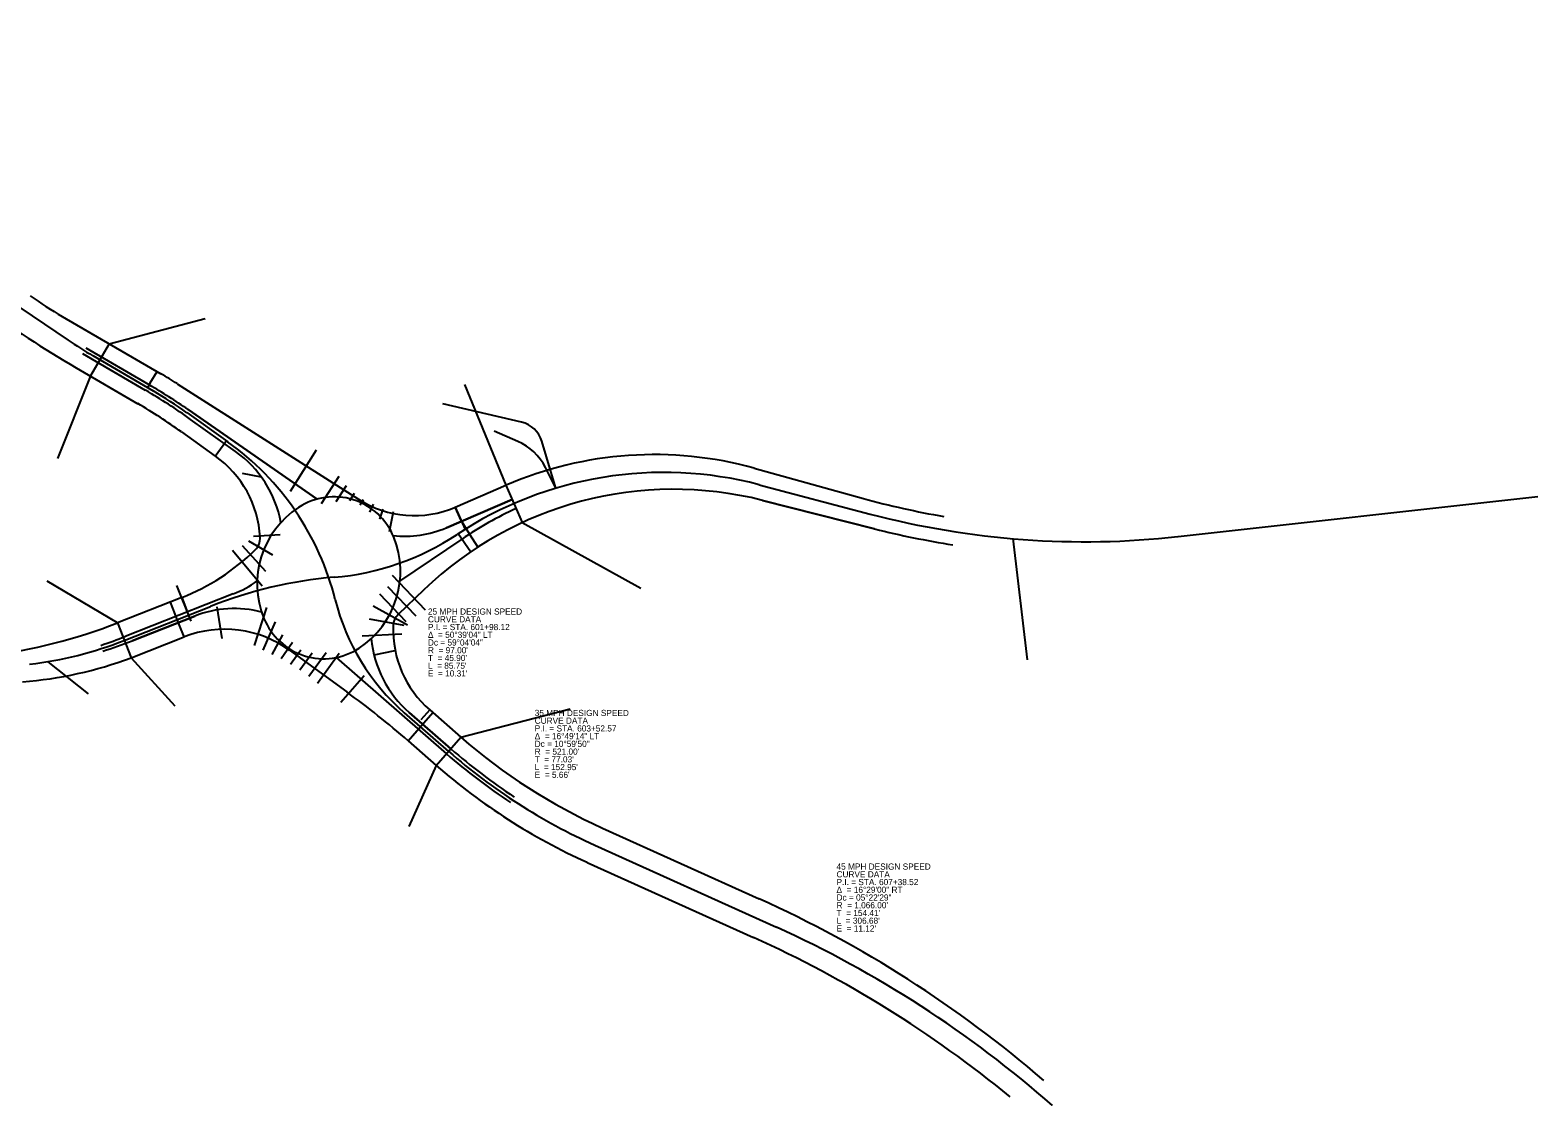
# Model space of a CAD drawing. Extents: x 1600028 to 1602104, y 285464 to 287187.
# Drawn here: x 1600738 to 1602104, y 286222 to 287187 of the extents above; entities that cross this region are included whole.
import ezdxf

# ---------------------------------------------------------------- set-up
doc = ezdxf.new("R2010")
doc.units = 0
for name, color, linetype in [('GE_P_Alignment', 7, 'Continuous'), ('GE_P_Driveway_CL', 7, 'Continuous'), ('SC_Scratch1', 7, 'Continuous'), ('SC_Scratch2', 7, 'Continuous'), ('SC_Scratch3', 7, 'Continuous'), ('SC_Scratch4', 7, 'Continuous'), ('SC_Scratch5', 7, 'Continuous'), ('SC_Scratch6', 7, 'Continuous'), ('SC_Scratch7', 7, 'Continuous')]:
    doc.layers.add(name, color=color, linetype=linetype)

msp = doc.modelspace()

# ---------------------------------------------------------------- linework, layer by layer
at = {"layer": 'GE_P_Alignment'}
for p, q in [((1600356.9, 287187.3), (1600772.5, 286906.6)), ((1600794.8, 286892.6), (1600849.5, 286860.7)), ((1600879.9, 286841), (1600916.9, 286814.6)), ((1601398.3, 286775.7), (1601499, 286749.2)), ((1601777.7, 286728.8), (1602103.6, 286765.1)), ((1600823.2, 286634.8), (1600901.3, 286665.6)), ((1601076.9, 286569.3), (1601117, 286534.3)), ((1601249.5, 286449.3), (1601413.9, 286375.1))]:
    msp.add_line(p, q, dxfattribs=at)
for centre, radius, start, end in [((1600996.4, 287238), 400, 235.9623, 239.7293), ((1600647.8, 286515.2), 400, 54.5316, 59.7293), ((1600771.8, 286611), 250, 14.0171, 54.5316), ((1601311.9, 286446.9), 340, 75.2715, 123.4087), ((1601693.2, 287488.1), 764, 255.2715, 276.3456), ((1600992.5, 286931), 240, 274.977, 303.4087), ((1601048.1, 286293.5), 400, 94.977, 111.5214), ((1601208.4, 286720), 200, 194.0171, 228.8864), ((1600697, 286954.8), 344, 276.7614, 291.5214), ((1601470.8, 286939.7), 538, 228.8864, 245.7068), ((1601002.5, 285463.6), 1000, 48.5834, 65.7068)]:
    msp.add_arc(centre, radius, start, end, dxfattribs=at)
at = {"layer": 'GE_P_Driveway_CL'}
for p, q in [((1601179.8, 286814.9), (1601158.3, 286824.1)), ((1601214.2, 286772.5), (1601204.7, 286791.4)), ((1601628, 286726.9), (1601641, 286617.1))]:
    msp.add_line(p, q, dxfattribs=at)
msp.add_arc((1601160, 286769), 50, 26.7021, 66.684, dxfattribs=at)
at = {"layer": 'SC_Scratch1'}
for p, q in [((1600809.6, 286903.4), (1600792.6, 286874.2)), ((1600846.8, 286867.9), (1600844.4, 286863.6)), ((1600846.8, 286867.9), (1600852.9, 286878.2)), ((1601183.1, 286832.4), (1601111.8, 286849.1)), ((1601183.1, 286832.4), (1601111.8, 286849.1)), ((1601214.2, 286772.5), (1601201.4, 286815.2)), ((1601214.2, 286772.5), (1601201.4, 286815.2)), ((1600905.7, 286801.7), (1600912.7, 286811.5)), ((1601168.9, 286775.3), (1601183.7, 286741.4)), ((1601123.1, 286755.5), (1601131.9, 286735.3)), ((1601128.7, 286742.7), (1601123.1, 286755.5)), ((1601125.8, 286731.5), (1601137.1, 286715)), ((1601128.7, 286742.7), (1601135.9, 286731)), ((1601135.9, 286731), (1601143.5, 286719.2)), ((1600875.3, 286673.6), (1600879.7, 286662.4)), ((1600817, 286650.6), (1600829.5, 286619)), ((1600877.5, 286637.9), (1600873.1, 286649.1)), ((1601080.3, 286543.8), (1601102.7, 286569.4)), ((1601099.9, 286571.8), (1601092, 286562.8)), ((1601080.3, 286543.8), (1601088.2, 286552.8)), ((1601105.9, 286521.5), (1601128.2, 286547.1))]:
    msp.add_line(p, q, dxfattribs=at)
for points in [[(1600905.7, 286801.7), (1600912.7, 286811.5), (1600915.6, 286815.6)], [(1600877.5, 286637.9), (1600873.1, 286649.1), (1600871.3, 286653.7), (1600869.4, 286658.4), (1600865, 286669.5)]]:
    msp.add_lwpolyline(points, dxfattribs=at)
msp.add_arc((1601177.4, 286808), 25, 16.7021, 76.8115, dxfattribs=at)
msp.add_arc((1601177.4, 286808), 25, 16.7021, 76.8115, dxfattribs=at)
at = {"layer": 'SC_Scratch2'}
for p, q in [((1600947.5, 286782.5), (1600930.2, 286785.9)), ((1601017.7, 286783.3), (1601001.7, 286758.3)), ((1601024.1, 286774.8), (1601015, 286760.4)), ((1601031.4, 286767.7), (1601027.3, 286761.2)), ((1601039.7, 286762.1), (1601036.7, 286757.1)), ((1601048.6, 286758.2), (1601045.4, 286750.9)), ((1601057.4, 286753.6), (1601054.5, 286744.7)), ((1601066.9, 286751.3), (1601063.1, 286733)), ((1600940.4, 286729.1), (1600964.3, 286730.7)), ((1600930, 286720.7), (1600951.3, 286697.5)), ((1600935.8, 286724.8), (1600957.4, 286712.2)), ((1600921.3, 286716.4), (1600948.1, 286684.2)), ((1601096.2, 286662.1), (1601066.2, 286693.4)), ((1601078.6, 286651.6), (1601054.7, 286676.5)), ((1601087.6, 286656.7), (1601062.1, 286683.3)), ((1600941.3, 286630.2), (1600952.3, 286664.6)), ((1601079.7, 286648.6), (1601048.8, 286665.9)), ((1600949.2, 286625.8), (1600960.3, 286651.6)), ((1601076.9, 286648.3), (1601045.3, 286654)), ((1600957.2, 286622.1), (1600967, 286639.8)), ((1601074.8, 286640.5), (1601038.6, 286638.7)), ((1600965.3, 286618.4), (1600975.7, 286633.3)), ((1600973.8, 286613.4), (1600983.1, 286626.2)), ((1600982.3, 286608), (1600993.5, 286623.5)), ((1600990.5, 286602.3), (1601006, 286623.7)), ((1600998.4, 286596.2), (1601018, 286623.2)), ((1601049.5, 286621.6), (1601068.7, 286625.5))]:
    msp.add_line(p, q, dxfattribs=at)
at = {"layer": 'SC_Scratch3'}
for p, q in [((1600997.2, 286807.1), (1600973.4, 286769.6)), ((1600912, 286636.4), (1600907.5, 286665.1)), ((1601040.5, 286602.7), (1601019.4, 286578.6))]:
    msp.add_line(p, q, dxfattribs=at)
at = {"layer": 'SC_Scratch4'}
msp.add_line((1600753.9, 286615.5), (1600790.4, 286586.4), dxfattribs=at)
at = {"layer": 'SC_Scratch5'}
for p, q in [((1600809.6, 286903.4), (1600896.4, 286926.2)), ((1600792.6, 286874.2), (1600762.7, 286799.5)), ((1601169.1, 286775.3), (1601131.8, 286866.5)), ((1601183.7, 286741.4), (1601291, 286682)), ((1600817, 286650.6), (1600753.4, 286688.4)), ((1600829.5, 286619), (1600869.1, 286575.6)), ((1601128.2, 286547.1), (1601227, 286572.9)), ((1601105.9, 286521.5), (1601081, 286466.3))]:
    msp.add_line(p, q, dxfattribs=at)
at = {"layer": 'SC_Scratch6'}
for p, q in [((1600767.1, 286928.1), (1600856.5, 286876.1)), ((1600845.8, 286866.1), (1600788.7, 286899.3)), ((1600845.8, 286866.1), (1600788.7, 286899.3)), ((1600779.7, 286881.7), (1600835.5, 286849.1)), ((1600842.5, 286861.2), (1600785.8, 286894.3)), ((1600842.5, 286861.2), (1600785.8, 286894.3)), ((1600871.1, 286867.2), (1601035.4, 286762.6)), ((1600881.1, 286843.8), (1600997.9, 286762.8)), ((1600997.9, 286762.8), (1600881.1, 286843.8)), ((1600924, 286805.9), (1600883.3, 286834.9)), ((1600924, 286805.9), (1600883.3, 286834.9)), ((1600875.2, 286823.5), (1600905.7, 286801.7)), ((1601393.7, 286790.8), (1601492.7, 286763.4)), ((1601393.7, 286790.8), (1601492.7, 286763.4)), ((1601123.1, 286755.5), (1601168.9, 286775.3)), ((1601174.6, 286762.5), (1601115, 286736.8)), ((1601115, 286736.8), (1601174.6, 286762.5)), ((1601502.8, 286735.9), (1601401.2, 286761.6)), ((1601401.2, 286761.6), (1601502.8, 286735.9)), ((1601072.9, 286688.3), (1601129.2, 286726.5)), ((1601072.9, 286688.3), (1601129.2, 286726.5)), ((1600922, 286677), (1600824.2, 286638.4)), ((1600922, 286677), (1600824.2, 286638.4)), ((1601094.7, 286680.6), (1601071.4, 286658.3)), ((1600875.3, 286673.6), (1600817, 286650.6)), ((1600830.4, 286634.4), (1600887.2, 286656.8)), ((1600887.2, 286656.8), (1600830.4, 286634.4)), ((1600829.5, 286619), (1600877.5, 286637.9)), ((1600973, 286625.8), (1601024.7, 286588.2)), ((1601015.1, 286619.3), (1601115.1, 286532.1)), ((1601119, 286536.6), (1601081.3, 286569.5)), ((1601081.3, 286569.5), (1601119, 286536.6)), ((1601099.9, 286571.8), (1601128.2, 286547.1)), ((1601080.3, 286543.8), (1601105.9, 286521.5)), ((1601256.5, 286464.8), (1601398.3, 286400.8)), ((1601256.5, 286464.8), (1601398.3, 286400.8)), ((1601242.5, 286433.8), (1601393.3, 286365.7)), ((1601242.5, 286433.8), (1601393.3, 286365.7))]:
    msp.add_line(p, q, dxfattribs=at)
for centre, radius, start, end in [((1601317, 287802.3), 1066, 234.2314, 239.7293), ((1600968.1, 287273.9), 400, 234.8822, 239.8305), ((1600649.4, 286520), 412, 57.4535, 59.8305), ((1600572.9, 286399.2), 535, 54.5316, 59.7293), ((1600572.9, 286399.2), 535, 54.5316, 59.7293), ((1600574, 286398.4), 541, 55.4065, 59.8327), ((1600574, 286398.4), 541, 55.4065, 59.8327), ((1600572.9, 286399.2), 521, 54.5316, 59.7293), ((1600849.5, 286722.7), 97, 3.2876, 54.5316), ((1600864.8, 286722.8), 102, 10.5564, 54.5316), ((1600864.8, 286722.8), 102, 10.5564, 54.5316), ((1601303.3, 286464), 339, 74.5355, 113.3233), ((1601303.3, 286464), 339, 74.5355, 113.3233), ((1601013.2, 286706.4), 58.4, 22.0233, 123.241), ((1601013.2, 286706.4), 58.4, 22.0233, 123.241), ((1601085.9, 286841.8), 94, 237.5008, 293.3341), ((1601321, 286444.6), 327, 75.7969, 133.7922), ((1601693.2, 287488.1), 752, 254.5355, 260.2263), ((1601693.2, 287488.1), 752, 254.5355, 260.2263), ((1601026.6, 286685.8), 83, 123.241, 202.0233), ((1601026.6, 286685.8), 83, 123.241, 202.0233), ((1601321, 286444.6), 341, 114.7663, 124.2219), ((1601321, 286444.6), 341, 114.7663, 124.2219), ((1601077.7, 286823.1), 94, 263.2777, 293.3337), ((1601077.7, 286823.1), 94, 263.2777, 293.3337), ((1601693.2, 287488.1), 776, 255.7969, 261.1483), ((1601693.2, 287488.1), 776, 255.7969, 261.1483), ((1600931.3, 286727.4), 15, 314.3733, 3.2876), ((1600990.4, 286697.2), 83, 303.241, 22.0233), ((1600801.9, 286859.6), 200, 291.5214, 314.3733), ((1600884.6, 286771.8), 102, 291.5214, 305.418), ((1600884.6, 286771.8), 102, 291.5214, 305.418), ((1600923.1, 286565.6), 98, 75.5121, 111.5214), ((1600923.1, 286565.6), 98, 75.5121, 111.5214), ((1600640, 287105.7), 488.3, 277.0862, 291.2524), ((1600640, 287105.7), 488.3, 277.0862, 291.2524), ((1601003.9, 286676.6), 58.4, 202.0233, 303.241), ((1601003.9, 286676.6), 58.4, 202.0233, 303.241), ((1601081.7, 286647.4), 15, 133.7922, 178.2352), ((1600640, 287105.4), 502, 288.8333, 291.5214), ((1600640, 287105.4), 502, 288.8333, 291.5214), ((1600914.2, 286544.9), 100, 53.985, 111.5214), ((1601148.4, 286646.3), 102, 185.587, 228.8864), ((1601148.4, 286646.3), 102, 185.587, 228.8864), ((1601163.7, 286644.9), 97, 178.2352, 228.8864), ((1600703.1, 286957.2), 347, 286.8568, 291.5214), ((1600703.1, 286957.2), 347, 286.8568, 291.5214), ((1600703, 286958.7), 362.5, 274.4402, 290.4124), ((1600703, 286958.7), 362.5, 274.4402, 290.4124), ((1600554.3, 285941.1), 800, 48.8864, 53.985), ((1601470.8, 286939.7), 521, 228.8864, 245.7068), ((1601470.8, 286939.7), 521, 228.8864, 245.7068), ((1601470.8, 286939.7), 541, 228.8864, 236.6168), ((1601470.8, 286939.7), 535, 228.8864, 236.6168), ((1601470.8, 286939.7), 535, 228.8864, 236.6168), ((1601470.8, 286939.7), 555, 228.8864, 245.7068), ((1601470.8, 286939.7), 555, 228.8864, 245.7068), ((1600959.8, 285429.2), 1066, 49.2234, 65.7068), ((1600959.8, 285429.2), 1066, 49.2234, 65.7068), ((1600964.6, 285416), 1042, 50.6283, 65.7068), ((1600964.6, 285416), 1042, 50.6283, 65.7068)]:
    msp.add_arc(centre, radius, start, end, dxfattribs=at)
at = {"layer": 'SC_Scratch7'}
msp.add_line((1600883.7, 286652.2), (1600871, 286684.5), dxfattribs=at)

# ---------------------------------------------------------------- texts
at = {"layer": 'SC_Scratch1'}
for s, p in [('25 MPH DESIGN SPEED', (1601098.3, 286658.1)), ('CURVE DATA', (1601098.3, 286651.1)), ('P.I. = STA. 601+98.12', (1601098.3, 286644.1)), ('Δ  = 50°39\'04" LT', (1601098.3, 286637.1)), ('Dc = 59°04\'04"', (1601098.3, 286630.1)), ("T  = 45.90'", (1601098.3, 286616.1)), ("R  = 97.00'", (1601098.3, 286623.1)), ("L  = 85.75'", (1601098.3, 286609.1)), ("E  = 10.31'", (1601098.3, 286602.1)), ('35 MPH DESIGN SPEED', (1601195, 286566.3)), ('CURVE DATA', (1601195, 286559.3)), ('P.I. = STA. 603+52.57', (1601195, 286552.3)), ('Δ  = 16°49\'14" LT', (1601195, 286545.3)), ('Dc = 10°59\'50"', (1601195, 286538.3)), ("T  = 77.03'", (1601195, 286524.3)), ("R  = 521.00'", (1601195, 286531.3)), ("L  = 152.95'", (1601195, 286517.3)), ("E  = 5.66'", (1601195, 286510.3)), ('45 MPH DESIGN SPEED', (1601468.4, 286427.2)), ('CURVE DATA', (1601468.4, 286420.2)), ('P.I. = STA. 607+38.52', (1601468.4, 286413.2)), ('Δ  = 16°29\'00" RT', (1601468.4, 286406.2)), ('Dc = 05°22\'29"', (1601468.4, 286399.2)), ("T  = 154.41'", (1601468.4, 286385.2)), ("R  = 1,066.00'", (1601468.4, 286392.2)), ("L  = 306.68'", (1601468.4, 286378.2)), ("E  = 11.12'", (1601468.4, 286371.2))]:
    msp.add_text(s, height=5.6, dxfattribs=at).set_placement(p)

doc.saveas('drawing.dxf')
